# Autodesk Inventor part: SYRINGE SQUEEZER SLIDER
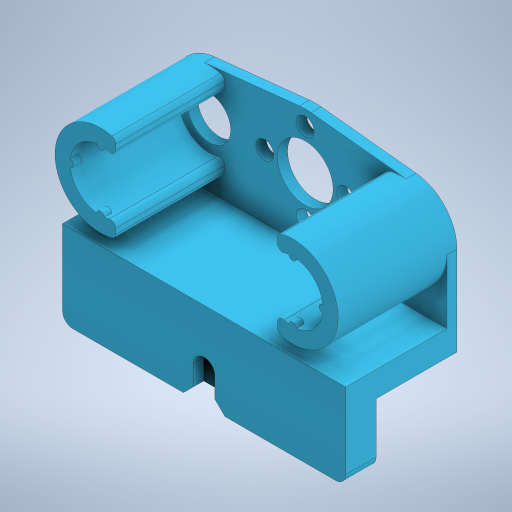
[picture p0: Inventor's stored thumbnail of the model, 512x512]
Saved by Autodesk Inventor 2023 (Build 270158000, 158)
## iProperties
Created: 2025-07
Part Number: SYRINGE SQUEEZER SLIDER
Material: Generic
Document SubType Name: Modeling
Designer: erjon
Density: 1 g/cm^3
Appearance: Turquoise
Author: erjon
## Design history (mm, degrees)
feature "Base1"
body "Solid1"
